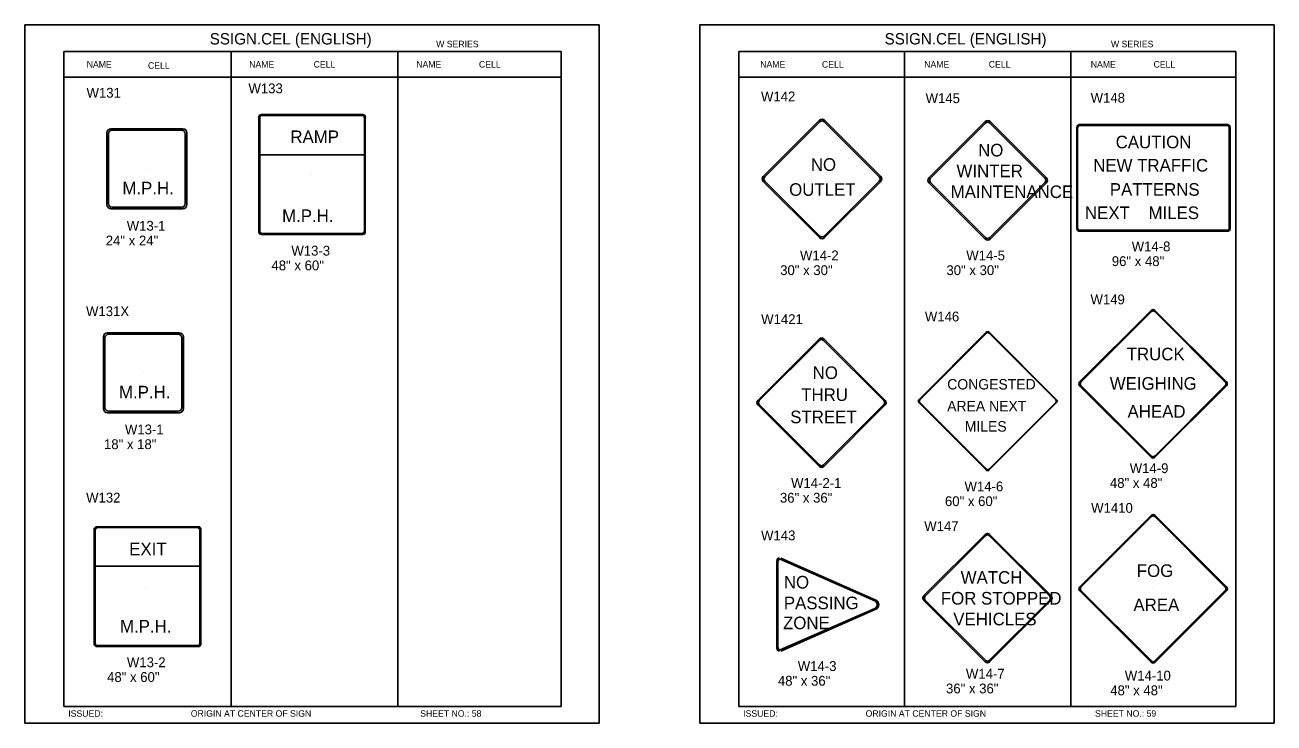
# Model space of a CAD drawing. Extents: x -5299 to 22597, y -19549 to -1808.
# Drawn here: x 2593 to 4118, y -6387 to -5535 of the extents above; entities that cross this region are included whole.
import ezdxf

# ---------------------------------------------------------------- set-up
doc = ezdxf.new("R2010")
doc.units = 0
for name, color, linetype in [('Level 1', 7, 'Continuous'), ('Level 2', 7, 'Continuous'), ('Level 3', 7, 'Continuous'), ('Level 62', 7, 'Continuous')]:
    doc.layers.add(name, color=color, linetype=linetype)

msp = doc.modelspace()

# ---------------------------------------------------------------- linework, layer by layer
at = {"layer": 'Level 1'}
for p, q in [((3247.7, -5567.2), (2640.7, -5567.2)), ((2640.7, -5567.2), (2640.7, -6367.2)), ((2845, -5567.2), (2845, -6367.2)), ((3048.2, -5567.2), (3048.2, -6367.2)), ((3247.7, -5567.2), (3247.7, -6367.2)), ((4071.6, -5567.2), (3464.6, -5567.2)), ((3464.6, -5567.2), (3464.6, -6367.2)), ((3667, -5567.2), (3667, -6367.2)), ((3870.1, -5567.2), (3870.1, -6367.2)), ((4071.6, -5567.2), (4071.6, -6367.2)), ((3247.7, -5598.9), (2640.7, -5598.9)), ((4071.6, -5598.9), (3464.6, -5598.9)), ((2878.6, -5787.8), (2878.6, -5647.3)), ((2878.6, -5787.8), (2878.6, -5647.3)), ((2879.9, -5786.9), (2879.9, -5648.2)), ((2879.9, -5786.9), (2879.9, -5648.2)), ((2881.9, -5644.4), (3005.5, -5644.4)), ((2881.9, -5644.4), (3005.5, -5644.4)), ((2882.8, -5645.5), (3004.5, -5645.5)), ((2882.8, -5645.5), (3004.5, -5645.5)), ((3007.5, -5648.2), (3007.5, -5786.9)), ((3007.5, -5648.2), (3007.5, -5786.9)), ((3008.7, -5647.3), (3008.7, -5787.8)), ((3008.7, -5647.3), (3008.7, -5787.8)), ((3494.6, -5720), (3563.3, -5651.3)), ((3496.6, -5720.3), (3563.6, -5653.3)), ((3569.1, -5653.3), (3636.1, -5720.3)), ((3569.3, -5651.3), (3638.1, -5720)), ((3696.9, -5721.8), (3765.6, -5653)), ((3698.9, -5722), (3765.9, -5655)), ((3771.3, -5655), (3838.3, -5722)), ((3771.6, -5653), (3840.3, -5721.8)), ((3879.8, -5656.7), (4062.2, -5656.7)), ((2693.2, -5754.4), (2693.2, -5666.6)), ((2693.2, -5754.4), (2693.2, -5666.6)), ((2695, -5753), (2695, -5668)), ((2695, -5753), (2695, -5668)), ((2698.1, -5661.7), (2785.9, -5661.7)), ((2698.1, -5661.7), (2785.9, -5661.7)), ((2699.5, -5663.6), (2784.4, -5663.6)), ((2699.5, -5663.6), (2784.4, -5663.6)), ((2788.9, -5668), (2788.9, -5753)), ((2788.9, -5668), (2788.9, -5753)), ((2790.7, -5666.6), (2790.7, -5754.4)), ((2790.7, -5666.6), (2790.7, -5754.4)), ((3877.5, -5783.6), (3877.5, -5660)), ((3878.4, -5782.6), (3878.4, -5660.9)), ((3880.5, -5657.9), (4061.5, -5657.9)), ((4063.6, -5660.9), (4063.6, -5782.6)), ((4064.5, -5660), (4064.5, -5783.6)), ((2879.9, -5693.4), (3007.5, -5693.4)), ((2879.9, -5693.4), (3007.5, -5693.4)), ((2741.6, -5711.1), (2741.6, -5711.1)), ((2943.2, -5718.1), (2943.2, -5718.1)), ((3563.3, -5794.7), (3494.6, -5726)), ((3563.6, -5792.7), (3496.6, -5725.7)), ((3566.3, -5722.5), (3566.3, -5722.5)), ((3636.1, -5725.7), (3569.1, -5792.7)), ((3638.1, -5726), (3569.3, -5794.7)), ((3765.6, -5796.5), (3696.9, -5727.7)), ((3765.9, -5794.5), (3698.9, -5727.5)), ((3768.8, -5724.8), (3768.8, -5724.8)), ((3838.3, -5727.5), (3771.3, -5794.5)), ((3840.3, -5727.7), (3771.6, -5796.5)), ((3968.5, -5724.3), (3968.5, -5724.3)), ((2785.9, -5759.3), (2698.1, -5759.3)), ((2785.9, -5759.3), (2698.1, -5759.3)), ((2784.4, -5757.5), (2699.5, -5757.5)), ((2784.4, -5757.5), (2699.5, -5757.5)), ((3005.5, -5790.7), (2881.9, -5790.7)), ((3005.5, -5790.7), (2881.9, -5790.7)), ((3004.5, -5789.6), (2882.8, -5789.6)), ((3004.5, -5789.6), (2882.8, -5789.6)), ((4062.2, -5786.8), (3879.8, -5786.8)), ((4061.5, -5785.6), (3880.5, -5785.6)), ((3880.8, -5970.9), (3968.2, -5883.5)), ((3882.4, -5971.1), (3968.4, -5885)), ((3972.6, -5885), (4058.7, -5971.1)), ((3972.8, -5883.5), (4060.2, -5970.9)), ((2689, -6003.6), (2689, -5915.8)), ((2693.8, -5910.9), (2781.7, -5910.9)), ((2695.3, -5912.7), (2780.2, -5912.7)), ((2786.6, -5915.8), (2786.6, -6003.6)), ((3684.4, -5992.6), (3766.9, -5910.2)), ((3685.6, -5992.7), (3767, -5911.3)), ((3770.2, -5911.3), (3851.6, -5992.7)), ((3770.3, -5910.2), (3852.7, -5992.6)), ((2690.8, -6002.2), (2690.8, -5917.2)), ((2784.7, -5917.2), (2784.7, -6002.2)), ((3487.9, -5993.5), (3563.1, -5918.4)), ((3489.7, -5993.7), (3563.3, -5920.2)), ((3568.2, -5920.2), (3641.7, -5993.7)), ((3568.4, -5918.4), (3643.5, -5993.5)), ((2737.6, -5958.9), (2737.6, -5958.9)), ((3968.2, -6062.9), (3880.8, -5975.5)), ((3968.4, -6061.4), (3882.4, -5975.3)), ((3970.2, -5973.3), (3970.2, -5973.3)), ((4058.7, -5975.3), (3972.6, -6061.4)), ((4060.2, -5975.5), (3972.8, -6062.9)), ((2781.7, -6008.5), (2693.8, -6008.5)), ((2780.2, -6006.6), (2695.3, -6006.6)), ((3563.1, -6074), (3487.9, -5998.8)), ((3563.3, -6072.2), (3489.7, -5998.6)), ((3565.6, -5996.1), (3565.6, -5996.1)), ((3641.7, -5998.6), (3568.2, -6072.2)), ((3643.5, -5998.8), (3568.4, -6074)), ((3766.9, -6078.4), (3684.5, -5996)), ((3767, -6077.3), (3685.6, -5995.9)), ((3768.5, -5994.4), (3768.5, -5994.4)), ((3851.6, -5995.9), (3770.2, -6077.3)), ((3852.7, -5996), (3770.3, -6078.4)), ((3880.9, -6221.2), (3968.3, -6133.8)), ((3882.4, -6221.4), (3968.5, -6135.3)), ((3972.7, -6135.3), (4058.7, -6221.4)), ((3972.9, -6133.8), (4060.3, -6221.2)), ((2677.8, -6291.1), (2677.8, -6150.6)), ((2677.8, -6291.1), (2677.8, -6150.6)), ((2679, -6290.3), (2679, -6151.5)), ((2679, -6290.3), (2679, -6151.5)), ((2681, -6147.7), (2804.6, -6147.7)), ((2681, -6147.7), (2804.6, -6147.7)), ((2682, -6148.8), (2803.6, -6148.8)), ((2682, -6148.8), (2803.6, -6148.8)), ((2806.6, -6151.5), (2806.6, -6290.3)), ((2806.6, -6151.5), (2806.6, -6290.3)), ((2807.8, -6150.6), (2807.8, -6291.1)), ((2807.8, -6150.6), (2807.8, -6291.1)), ((3690.4, -6232.1), (3765.6, -6157)), ((3692.2, -6232.4), (3765.8, -6158.8)), ((3770.7, -6158.8), (3844.3, -6232.4)), ((3770.9, -6157), (3846.1, -6232.1)), ((3511.1, -6295.9), (3511.1, -6189.6)), ((3512.3, -6294.8), (3512.3, -6190.7)), ((3515.3, -6187.3), (3630.6, -6238.1)), ((3515.9, -6186), (3632.1, -6237.2)), ((2679, -6195.7), (2806.6, -6195.7)), ((2679, -6195.7), (2806.6, -6195.7)), ((2741.6, -6221.7), (2741.6, -6221.7)), ((3765.8, -6310.8), (3692.2, -6237.3)), ((3768.2, -6234.3), (3768.2, -6234.3)), ((3844.3, -6237.3), (3770.7, -6310.8)), ((3968.3, -6313.2), (3880.9, -6225.8)), ((3968.5, -6311.6), (3882.4, -6225.6)), ((3970.2, -6223.6), (3970.2, -6223.6)), ((4058.7, -6225.6), (3972.7, -6311.6)), ((4060.3, -6225.8), (3972.9, -6313.2)), ((3630.6, -6247.4), (3515.3, -6298.2)), ((3632.1, -6248.3), (3515.9, -6299.5)), ((3572.3, -6242.5), (3572.3, -6242.5)), ((3765.6, -6312.6), (3690.4, -6237.5)), ((3846.1, -6237.5), (3770.9, -6312.6)), ((2804.6, -6294), (2681, -6294)), ((2804.6, -6294), (2681, -6294)), ((2803.6, -6292.9), (2682, -6292.9)), ((2803.6, -6292.9), (2682, -6292.9)), ((2640.7, -6367.2), (3247.7, -6367.2)), ((3464.6, -6367.2), (4071.6, -6367.2))]:
    msp.add_line(p, q, dxfattribs=at)
for centre, radius, start, end in [((3566.3, -5654.3), 4.23, 45, 135), ((3566.3, -5656), 3.87, 45, 135), ((3768.6, -5656), 4.23, 45, 135), ((3768.6, -5657.7), 3.87, 45, 135), ((2698.1, -5666.6), 4.88, 90, 180), ((2698.1, -5666.6), 4.88, 90, 180), ((2699.5, -5668), 4.47, 90, 180), ((2699.5, -5668), 4.47, 90, 180), ((2784.4, -5668), 4.47, 0, 90), ((2784.4, -5668), 4.47, 0, 90), ((2785.9, -5666.6), 4.88, 0, 90), ((2785.9, -5666.6), 4.88, 0, 90), ((3497.6, -5723), 4.23, 135, 225), ((3499.3, -5723), 3.87, 135, 225), ((3633.3, -5723), 3.87, 315, 45), ((3635.1, -5723), 4.23, 315, 45), ((3699.9, -5724.7), 4.23, 135, 225), ((3701.6, -5724.7), 3.87, 135, 225), ((3835.6, -5724.7), 3.87, 315, 45), ((3837.3, -5724.7), 4.23, 315, 45), ((2698.1, -5754.4), 4.88, 180, 270), ((2698.1, -5754.4), 4.88, 180, 270), ((2699.5, -5753), 4.47, 180, 270), ((2699.5, -5753), 4.47, 180, 270), ((2784.4, -5753), 4.47, 270, 0), ((2784.4, -5753), 4.47, 270, 0), ((2785.9, -5754.4), 4.88, 270, 0), ((2785.9, -5754.4), 4.88, 270, 0), ((3566.3, -5791.8), 4.23, 225, 315), ((3566.3, -5790), 3.87, 225, 315), ((3768.6, -5791.7), 3.87, 225, 315), ((3768.6, -5793.5), 4.23, 225, 315), ((3970.5, -5885.8), 3.25, 45, 135), ((3970.5, -5887.1), 2.98, 45, 135), ((2693.8, -5915.8), 4.88, 90, 180), ((2695.3, -5917.2), 4.47, 90, 180), ((2780.2, -5917.2), 4.47, 0, 90), ((2781.7, -5915.8), 4.88, 0, 90), ((3768.6, -5911.9), 2.43, 45, 135), ((3768.6, -5912.9), 2.23, 45, 135), ((3565.7, -5921.1), 3.79, 45, 135), ((3565.7, -5922.6), 3.48, 45, 135), ((3883.1, -5973.2), 3.25, 135, 225), ((3884.5, -5973.2), 2.98, 135, 225), ((4056.6, -5973.2), 2.98, 315, 45), ((4057.9, -5973.2), 3.25, 315, 45), ((3686.2, -5994.3), 2.43, 135, 225), ((3687.2, -5994.3), 2.23, 135, 225), ((3850, -5994.3), 2.23, 315, 45), ((3851, -5994.3), 2.43, 315, 45), ((2693.8, -6003.6), 4.88, 180, 270), ((2695.3, -6002.2), 4.47, 180, 270), ((2780.2, -6002.2), 4.47, 270, 0), ((2781.7, -6003.6), 4.88, 270, 0), ((3490.6, -5996.2), 3.79, 135, 225), ((3492.2, -5996.2), 3.48, 135, 225), ((3639.3, -5996.2), 3.48, 315, 45), ((3640.8, -5996.2), 3.79, 315, 45), ((3970.5, -6060.6), 3.25, 225, 315), ((3970.5, -6059.2), 2.98, 225, 315), ((3565.7, -6071.3), 3.79, 225, 315), ((3565.7, -6069.7), 3.48, 225, 315), ((3768.6, -6076.7), 2.43, 225, 315), ((3768.6, -6075.7), 2.23, 225, 315), ((3970.6, -6136.1), 3.25, 45, 135), ((3970.6, -6137.4), 2.98, 45, 135), ((3768.3, -6159.7), 3.8, 45, 135), ((3768.3, -6161.2), 3.48, 45, 135), ((3883.2, -6223.5), 3.25, 135, 225), ((3884.5, -6223.5), 2.98, 135, 225), ((4056.6, -6223.5), 2.98, 315, 45), ((4058, -6223.5), 3.25, 315, 45), ((3629.6, -6242.8), 6.09, 293.7876, 66.2099), ((3693.1, -6234.8), 3.8, 135, 225), ((3694.7, -6234.8), 3.48, 135, 225), ((3841.8, -6234.8), 3.48, 315, 45), ((3843.4, -6234.8), 3.8, 315, 45), ((3628.6, -6242.8), 5.08, 293.7878, 66.2098), ((3768.3, -6310), 3.8, 225, 315), ((3768.3, -6308.4), 3.48, 225, 315), ((3970.6, -6310.9), 3.25, 225, 315), ((3970.6, -6309.5), 2.98, 225, 315)]:
    msp.add_arc(centre, radius, start, end, dxfattribs=at)
for centre, major_axis, ratio, start_param, end_param in [((2881.9, -5647.3), (-3.25, 0), 0.9, 4.712389, 6.283185), ((2881.9, -5647.3), (-3.25, 0), 0.9, 4.712389, 6.283185), ((2882.8, -5648.2), (-2.98, 0), 0.9, 4.712389, 6.283185), ((2882.8, -5648.2), (-2.98, 0), 0.9, 4.712389, 6.283185), ((3004.5, -5648.2), (-2.98, 0), 0.9, 3.141593, 4.712389), ((3004.5, -5648.2), (-2.98, 0), 0.9, 3.141593, 4.712389), ((3005.5, -5647.3), (-3.25, 0), 0.9, 3.141593, 4.712389), ((3005.5, -5647.3), (-3.25, 0), 0.9, 3.141593, 4.712389), ((3879.8, -5660), (0, -3.25), 0.71875, 3.141593, 4.712389), ((4062.2, -5660), (0, 3.25), 0.71875, 4.712389, 6.283185), ((3880.5, -5660.9), (0, -2.98), 0.71875, 3.141593, 4.712389), ((4061.5, -5660.9), (0, 2.98), 0.71875, 4.712389, 6.283185), ((2881.9, -5787.8), (-3.25, 0), 0.9, 0, 1.570796), ((2881.9, -5787.8), (-3.25, 0), 0.9, 0, 1.570796), ((2882.8, -5786.9), (2.98, 0), 0.9, 3.141593, 4.712389), ((2882.8, -5786.9), (2.98, 0), 0.9, 3.141593, 4.712389), ((3004.5, -5786.9), (2.98, 0), 0.9, 4.712389, 6.283185), ((3004.5, -5786.9), (2.98, 0), 0.9, 4.712389, 6.283185), ((3005.5, -5787.8), (3.25, 0), 0.9, 4.712389, 6.283185), ((3005.5, -5787.8), (3.25, 0), 0.9, 4.712389, 6.283185), ((3879.8, -5783.6), (0, -3.25), 0.71875, 4.712389, 6.283185), ((3880.5, -5782.6), (0, -2.98), 0.71875, 4.712389, 6.283185), ((4061.5, -5782.6), (0, -2.98), 0.71875, 0, 1.570796), ((4062.2, -5783.6), (0, -3.25), 0.71875, 0, 1.570796), ((2681, -6150.6), (-3.25, 0), 0.9, 4.712389, 6.283185), ((2681, -6150.6), (-3.25, 0), 0.9, 4.712389, 6.283185), ((2682, -6151.5), (-2.98, 0), 0.9, 4.712389, 6.283185), ((2682, -6151.5), (-2.98, 0), 0.9, 4.712389, 6.283185), ((2803.6, -6151.5), (-2.98, 0), 0.9, 3.141593, 4.712389), ((2803.6, -6151.5), (-2.98, 0), 0.9, 3.141593, 4.712389), ((2804.6, -6150.6), (-3.25, 0), 0.9, 3.141593, 4.712389), ((2804.6, -6150.6), (-3.25, 0), 0.9, 3.141593, 4.712389), ((3514.4, -6189.6), (0, 3.79), 0.857082, 0, 1.570796), ((3515.3, -6190.7), (0, -3.48), 0.857082, 3.141593, 4.712389), ((2681, -6291.1), (-3.25, 0), 0.9, 0, 1.570796), ((2681, -6291.1), (-3.25, 0), 0.9, 0, 1.570796), ((2682, -6290.3), (2.98, 0), 0.9, 3.141593, 4.712389), ((2682, -6290.3), (2.98, 0), 0.9, 3.141593, 4.712389), ((2803.6, -6290.3), (2.98, 0), 0.9, 4.712389, 6.283185), ((2803.6, -6290.3), (2.98, 0), 0.9, 4.712389, 6.283185), ((2804.6, -6291.1), (3.25, 0), 0.9, 4.712389, 6.283185), ((2804.6, -6291.1), (3.25, 0), 0.9, 4.712389, 6.283185), ((3514.4, -6295.9), (0, -3.79), 0.857082, 4.712389, 6.283185), ((3515.3, -6294.8), (0, -3.48), 0.857082, 4.712389, 6.283185)]:
    msp.add_ellipse(centre, major_axis=major_axis, ratio=ratio, start_param=start_param, end_param=end_param, dxfattribs=at)
at = {"layer": 'Level 62'}
for points in [[(2593.1, -6387.4), (3294.2, -6387.4), (3294.2, -5535), (2593.1, -5535)], [(3417.1, -6387.4), (4118.2, -6387.4), (4118.2, -5535), (3417.1, -5535)]]:
    msp.add_lwpolyline(points, close=True, dxfattribs=at)

# ---------------------------------------------------------------- texts
at = {"layer": 'Level 1'}
for s, height, p in [('RAMP', 15.36, (2917.2, -5679.2)), ('RAMP', 15.36, (2917.2, -5679.2)), ('CAUTION', 15.37, (3924.8, -5685.6)), ('NO', 15.36, (3756.9, -5695.5)), ('NO', 15.36, (3552.6, -5713.1)), ('NEW TRAFFIC', 15.368, (3897.4, -5714)), ('WINTER', 15.36, (3730.5, -5720.9)), ('M.P.H.', 15.36, (2712.1, -5741.8)), ('M.P.H.', 15.36, (2712.1, -5741.8)), ('OUTLET', 15.36, (3526.2, -5743.6)), ('MAINTENANCE', 15.363, (3723.4, -5746.3)), ('PATTERNS', 15.37, (3917.7, -5743.5)), ('M.P.H.', 15.36, (2907.1, -5775.6)), ('M.P.H.', 15.36, (2907.1, -5775.6)), ('NEXT    MILES', 15.368, (3887.3, -5772)), ('TRUCK', 15.37, (3938.3, -5944.5)), ('NO', 15.36, (3554.9, -5967.3)), ('M.P.H.', 15.37, (2707.9, -5991)), ('CONGESTED', 12.75, (3719.2, -5980.1)), ('WEIGHING', 15.37, (3917.6, -5980.4)), ('THRU', 15.36, (3540.9, -5994.1)), ('STREET', 15.36, (3527.5, -6021.3)), ('AREA NEXT', 12.75, (3719.1, -6006.8)), ('AHEAD', 15.37, (3939.3, -6014.6)), ('  MILES', 12.75, (3731.1, -6031.5)), ('EXIT', 15.36, (2720.4, -6182.5)), ('EXIT', 15.36, (2720.4, -6182.5)), ('WATCH', 15.37, (3735.6, -6217.3)), ('FOG', 15.37, (3950.6, -6209)), ('NO', 15.36, (3519.7, -6223.1)), ('PASSING', 15.36, (3519.7, -6248.4)), ('FOR STOPPED', 15.368, (3711.4, -6242.7)), ('AREA', 15.37, (3946.5, -6250.7)), ('VEHICLES', 15.37, (3726.6, -6268.1)), ('M.P.H.', 15.36, (2709.2, -6276.9)), ('M.P.H.', 15.36, (2709.2, -6276.9)), ('ZONE', 15.36, (3518.7, -6272.8))]:
    msp.add_text(s, height=height, dxfattribs=at).set_placement(p)
at = {"layer": 'Level 2'}
for s, p in [('W131', (2668.3, -5623.8)), ('W133', (2866, -5618.4)), ('W142', (3491.8, -5628.3)), ('W145', (3692.8, -5630.4)), ('W148', (3894.3, -5629.9)), ('W149', (3894.1, -5876.1)), ('W131X', (2667.7, -5890.5)), ('W146', (3691.9, -5897)), ('W1421', (3492, -5900.2)), ('W132', (2667.8, -6118.1)), ('W1410', (3894.9, -6130.7)), ('W147', (3691.1, -6153)), ('W143', (3491.9, -6164.3))]:
    msp.add_text(s, height=12, dxfattribs=at).set_placement(p)
at = {"layer": 'Level 3'}
for s, height, p in [('SSIGN.CEL (ENGLISH)', 13.857, (2818.7, -5558.8)), ('SSIGN.CEL (ENGLISH)', 13.857, (3642.7, -5558.8)), ('W SERIES', 7.92, (3095.2, -5562.2)), ('W SERIES', 7.92, (3919.1, -5562.2)), ('NAME', 7.92, (2668.5, -5587)), ('CELL', 7.92, (2743.3, -5588.4)), ('NAME', 7.92, (2866.9, -5587)), ('CELL', 7.92, (2945.6, -5587)), ('NAME', 7.92, (3070.9, -5587)), ('CELL', 7.92, (3147.4, -5587)), ('NAME', 7.92, (3490.9, -5587)), ('CELL', 7.92, (3566.2, -5587)), ('NAME', 7.92, (3691.1, -5587)), ('CELL', 7.92, (3769.9, -5587)), ('NAME', 7.92, (3894.4, -5587)), ('CELL', 7.92, (3971.1, -5587)), ('W13-1', 12, (2717.4, -5786.2)), ('24" x 24"', 12, (2691.8, -5804.2)), ('W13-3', 12, (2918.4, -5816.6)), ('W14-2', 12, (3539.4, -5822.4)), ('W14-8', 12, (3944.4, -5811.4)), ('48" x 60"', 12, (2894.1, -5834.6)), ('W14-5', 12, (3742.4, -5822.4)), ('96" x 48"', 12, (3920.1, -5829.4)), ('30" x 30"', 12, (3515.2, -5840.4)), ('30" x 30"', 12, (3718.2, -5840.4)), ('W13-1', 12, (2715.2, -6034.9)), ('18" x 18"', 12, (2689.6, -6052.9)), ('W14-9', 12, (3942, -6082.2)), ('W14-2-1', 12, (3528.5, -6100.3)), ('W14-6', 12, (3740.3, -6104.5)), ('48" x 48"', 12, (3917.8, -6100.2)), ('36" x 36"', 12, (3514.9, -6118.3)), ('60" x 60"', 12, (3716.4, -6122.5)), ('W13-2', 12, (2717.6, -6319.2)), ('W14-3', 12, (3536.7, -6323.8)), ('48" x 60"', 12, (2693.4, -6337.2)), ('W14-7', 12, (3742, -6333.2)), ('W14-10', 12, (3936, -6335.5)), ('48" x 36"', 12, (3512.4, -6341.8)), ('36" x 36"', 12, (3717.7, -6351.2)), ('48" x 48"', 12, (3918.2, -6353.5)), ('ISSUED:', 7.92, (2646, -6379.7)), ('ORIGIN AT CENTER OF SIGN', 7.918, (2795.6, -6379.7)), ('SHEET NO.: 58', 7.918, (3075.7, -6379.7)), ('ISSUED:', 7.92, (3470, -6379.7)), ('ORIGIN AT CENTER OF SIGN', 7.918, (3619.5, -6379.7)), ('SHEET NO.: 59', 7.918, (3899.6, -6379.7))]:
    msp.add_text(s, height=height, dxfattribs=at).set_placement(p)

doc.saveas('drawing.dxf')
